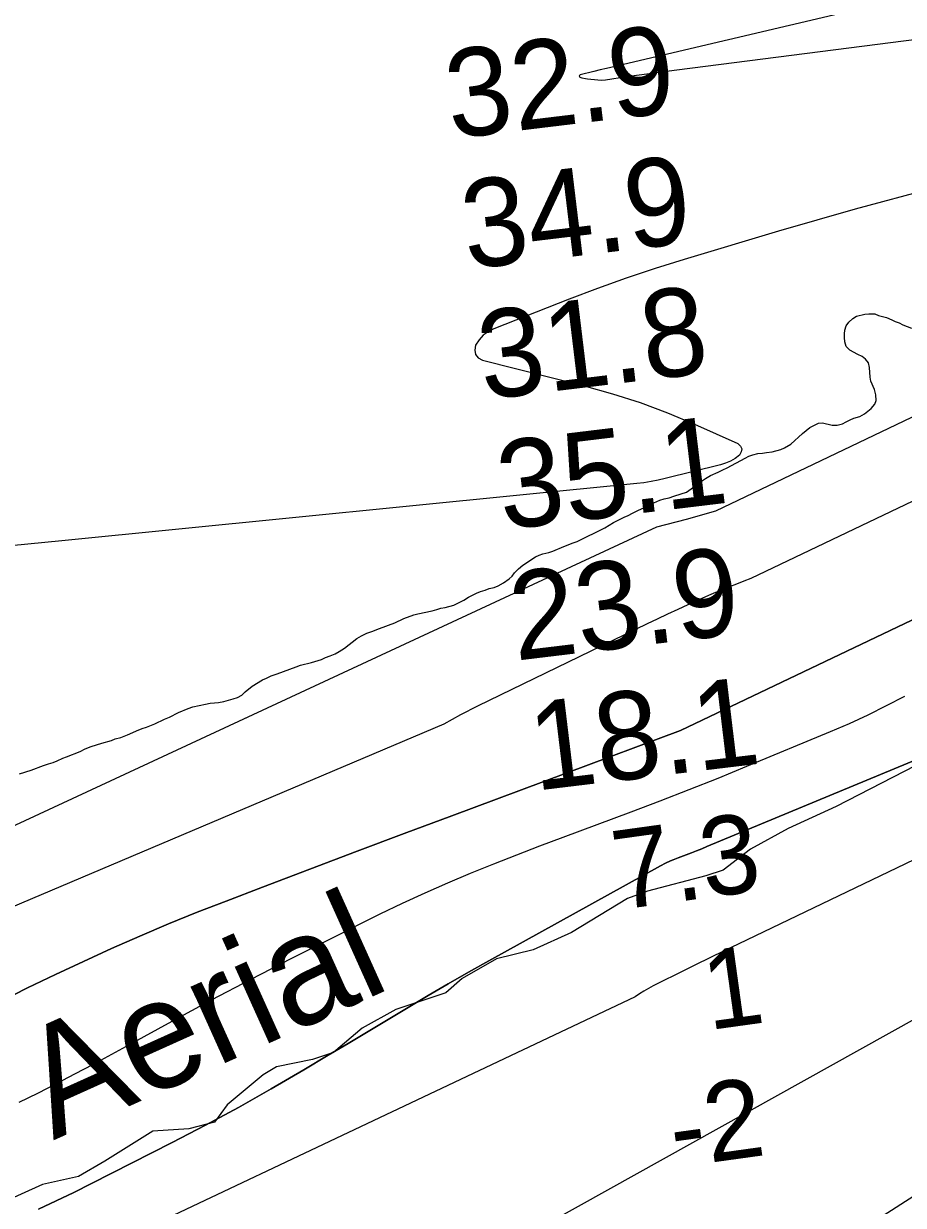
# Model space of a CAD drawing. Extents: x 3219052 to 3256913, y 800770 to 826146.
# Drawn here: x 3224915 to 3225585, y 815967 to 816866 of the extents above; entities that cross this region are included whole.
import ezdxf

# ---------------------------------------------------------------- set-up
doc = ezdxf.new("R2010")
doc.units = 0
for name, color, linetype in [('V-RIVR-EDGE', 7, 'Continuous'), ('V-RIVR-IDEN', 7, 'Continuous'), ('V-RIVR-RANG', 7, 'Continuous'), ('V-SITE-VEGE', 7, 'Continuous'), ('V-TOPO-DPTH', 7, 'Continuous'), ('V-TOPO-MAJR', 7, 'Continuous'), ('V-TOPO-MINR', 7, 'Continuous'), ('V-TOPO-WATR', 7, 'Continuous')]:
    doc.layers.add(name, color=color, linetype=linetype)

msp = doc.modelspace()

# ---------------------------------------------------------------- linework, layer by layer
at = {"layer": 'V-RIVR-EDGE'}
msp.add_lwpolyline([(3225602.27, 816305.95), (3225533.5, 816270.48), (3225496.95, 816253.61), (3225468.22, 816238.04), (3225447.32, 816222.01), (3225434.27, 816217.69), (3225389.9, 816206.06), (3225374.67, 816200.45), (3225332.01, 816174.48), (3225302.85, 816161.51), (3225275.02, 816154.62), (3225248.9, 816139.47), (3225236.27, 816128.64), (3225198.42, 816116.12), (3225172.74, 816101.84), (3225150.96, 816083.21), (3225134.86, 816078.03), (3225107.46, 816072.45), (3225097.45, 816066.39), (3225070.01, 816043.42), (3225060.41, 816030.4), (3225040.84, 816025.23), (3225013.45, 816023.56), (3224976.88, 816000.61), (3224956.86, 815988.93), (3224929.46, 815982.91), (3224899.87, 815969.51)], dxfattribs=at)
at = {"layer": 'V-SITE-VEGE'}
for p, q in [((3225546.11, 816641.72), (3225548.95, 816643.43)), ((3225548.95, 816643.43), (3225555.15, 816645)), ((3225555.15, 816645), (3225558.33, 816645.2)), ((3225558.33, 816645.2), (3225562.86, 816645.08)), ((3225562.86, 816645.08), (3225565.56, 816643.94)), ((3225565.56, 816643.94), (3225571.62, 816642.32)), ((3225540, 816632.76), (3225540.98, 816635.96)), ((3225540.98, 816635.96), (3225542.96, 816638.83)), ((3225542.96, 816638.83), (3225546.11, 816641.72)), ((3225571.62, 816642.32), (3225575.67, 816640.69)), ((3225575.67, 816640.69), (3225578.36, 816639.37)), ((3225578.36, 816639.37), (3225581.4, 816638.23)), ((3225581.4, 816638.23), (3225584.09, 816636.92)), ((3225584.09, 816636.92), (3225590.67, 816634.3)), ((3225539.7, 816630.07), (3225540, 816632.76)), ((3225539.73, 816627.22), (3225539.7, 816630.07)), ((3225539.93, 816623.86), (3225539.73, 816627.22)), ((3225540.97, 816620.35), (3225539.93, 816623.86)), ((3225543.85, 816617.53), (3225540.97, 816620.35)), ((3225549.76, 816614.23), (3225543.85, 816617.53)), ((3225553.14, 816612.76), (3225549.76, 816614.23)), ((3225555.67, 816610.77), (3225553.14, 816612.76)), ((3225557.89, 816607.78), (3225555.67, 816610.77)), ((3225558.76, 816604.26), (3225557.89, 816607.78)), ((3225559.34, 816597.05), (3225558.76, 816604.26)), ((3225559.71, 816594.03), (3225559.34, 816597.05)), ((3225562.46, 816587.52), (3225559.71, 816594.03)), ((3225563.51, 816583.67), (3225562.46, 816587.52)), ((3225563.9, 816579.31), (3225563.51, 816583.67)), ((3225554.94, 816569.15), (3225557.44, 816571.19)), ((3225557.44, 816571.19), (3225560.1, 816573.06)), ((3225560.1, 816573.06), (3225562.75, 816576.45)), ((3225562.75, 816576.45), (3225563.9, 816579.31)), ((3225516.94, 816560.52), (3225519.94, 816561.9)), ((3225519.94, 816561.9), (3225522.96, 816562.26)), ((3225522.96, 816562.26), (3225530.36, 816560.5)), ((3225538.07, 816561.42), (3225541.07, 816562.96)), ((3225541.07, 816562.96), (3225544.08, 816564.67)), ((3225544.08, 816564.67), (3225546.92, 816565.71)), ((3225546.92, 816565.71), (3225551.44, 816567.1)), ((3225551.44, 816567.1), (3225554.94, 816569.15)), ((3225498.8, 816546.07), (3225507.77, 816554.05)), ((3225507.77, 816554.05), (3225513.43, 816558.64)), ((3225513.43, 816558.64), (3225516.94, 816560.52)), ((3225530.36, 816560.5), (3225534.22, 816560.37)), ((3225534.22, 816560.37), (3225538.07, 816561.42)), ((3225494.13, 816543.33), (3225498.8, 816546.07)), ((3225450.32, 816527.93), (3225464.17, 816535.29)), ((3225464.17, 816535.29), (3225467.01, 816537.01)), ((3225467.01, 816537.01), (3225469.85, 816538.04)), ((3225469.85, 816538.04), (3225473.87, 816538.92)), ((3225473.87, 816538.92), (3225477.22, 816539.12)), ((3225477.22, 816539.12), (3225480.41, 816539.66)), ((3225480.41, 816539.66), (3225484.76, 816540.21)), ((3225484.76, 816540.21), (3225491.29, 816541.96)), ((3225491.29, 816541.96), (3225494.13, 816543.33)), ((3225443.64, 816524.84), (3225447.15, 816526.56)), ((3225447.15, 816526.56), (3225450.32, 816527.93)), ((3225423.13, 816512.04), (3225429.29, 816516.8)), ((3225429.29, 816516.8), (3225433.96, 816519.87)), ((3225433.96, 816519.87), (3225437.63, 816522.09)), ((3225437.63, 816522.09), (3225443.64, 816524.84)), ((3225409.77, 816506.53), (3225415.46, 816508.27)), ((3225415.46, 816508.27), (3225419.47, 816509.65)), ((3225419.47, 816509.65), (3225423.13, 816512.04)), ((3225389.38, 816498.76), (3225392.38, 816500.47)), ((3225392.38, 816500.47), (3225399.23, 816503.4)), ((3225399.23, 816503.4), (3225402.58, 816504.44)), ((3225402.58, 816504.44), (3225406.26, 816505.32)), ((3225406.26, 816505.32), (3225409.77, 816506.53)), ((3225363.83, 816486.41), (3225372.18, 816490.53)), ((3225372.18, 816490.53), (3225375.02, 816491.73)), ((3225375.02, 816491.73), (3225378.36, 816493.44)), ((3225378.36, 816493.44), (3225389.38, 816498.76)), ((3225336.29, 816472.02), (3225357.33, 816482.31)), ((3225357.33, 816482.31), (3225363.83, 816486.41)), ((3225333.29, 816470.98), (3225336.29, 816472.02)), ((3225310.21, 816462.68), (3225314.73, 816463.74)), ((3225314.73, 816463.74), (3225317.75, 816464.61)), ((3225317.75, 816464.61), (3225326.27, 816468.22)), ((3225326.27, 816468.22), (3225333.29, 816470.98)), ((3225291.54, 816451.24), (3225295.04, 816453.96)), ((3225295.04, 816453.96), (3225297.7, 816455.84)), ((3225297.7, 816455.84), (3225301.7, 816458.57)), ((3225301.7, 816458.57), (3225304.53, 816460.28)), ((3225304.53, 816460.28), (3225307.37, 816461.65)), ((3225307.37, 816461.65), (3225310.21, 816462.68)), ((3225284.57, 816443.62), (3225286.9, 816445.66)), ((3225286.9, 816445.66), (3225288.72, 816448.19)), ((3225288.72, 816448.19), (3225291.54, 816451.24)), ((3225266.2, 816435.03), (3225269.38, 816436.24)), ((3225269.38, 816436.24), (3225273.23, 816437.12)), ((3225273.23, 816437.12), (3225276.24, 816438.33)), ((3225276.24, 816438.33), (3225280.24, 816440.55)), ((3225280.24, 816440.55), (3225284.57, 816443.62)), ((3225242.5, 816423.54), (3225250.01, 816427.31)), ((3225250.01, 816427.31), (3225253.67, 816429.7)), ((3225253.67, 816429.7), (3225259.68, 816432.78)), ((3225259.68, 816432.78), (3225262.86, 816433.99)), ((3225262.86, 816433.99), (3225266.2, 816435.03)), ((3225215.04, 816417.04), (3225225.93, 816419.34)), ((3225225.93, 816419.34), (3225229.44, 816420.21)), ((3225229.44, 816420.21), (3225232.45, 816421.25)), ((3225232.45, 816421.25), (3225235.8, 816421.79)), ((3225235.8, 816421.79), (3225242.5, 816423.54)), ((3225192.65, 816408.24), (3225197.5, 816410.14)), ((3225197.5, 816410.14), (3225204.34, 816413.4)), ((3225204.34, 816413.4), (3225212.03, 816416.17)), ((3225212.03, 816416.17), (3225215.04, 816417.04)), ((3225168.59, 816398.26), (3225172.26, 816400.31)), ((3225172.26, 816400.31), (3225176.26, 816402.37)), ((3225176.26, 816402.37), (3225180.78, 816403.76)), ((3225180.78, 816403.76), (3225183.79, 816405.13)), ((3225183.79, 816405.13), (3225192.65, 816408.24)), ((3225159.27, 816390.77), (3225168.59, 816398.26)), ((3225134.21, 816379.94), (3225141.74, 816382.37)), ((3225141.74, 816382.37), (3225144.75, 816383.74)), ((3225144.75, 816383.74), (3225148.42, 816385.12)), ((3225148.42, 816385.12), (3225152.1, 816386.67)), ((3225152.1, 816386.67), (3225155.27, 816388.38)), ((3225155.27, 816388.38), (3225159.27, 816390.77)), ((3225108.12, 816371.44), (3225122.5, 816376.79)), ((3225122.5, 816376.79), (3225125.67, 816377.83)), ((3225125.67, 816377.83), (3225134.21, 816379.94)), ((3225089.09, 816362.01), (3225096.76, 816366.79)), ((3225096.76, 816366.79), (3225099.94, 816368.16)), ((3225099.94, 816368.16), (3225103.44, 816369.88)), ((3225103.44, 816369.88), (3225108.12, 816371.44)), ((3225077.94, 816353.33), (3225081.11, 816355.04)), ((3225081.11, 816355.04), (3225083.6, 816357.59)), ((3225083.6, 816357.59), (3225089.09, 816362.01)), ((3225040.27, 816345.05), (3225043.78, 816346.26)), ((3225043.78, 816346.26), (3225053.49, 816348.37)), ((3225053.49, 816348.37), (3225057.01, 816348.92)), ((3225057.01, 816348.92), (3225060.36, 816349.29)), ((3225060.36, 816349.29), (3225063.38, 816349.48)), ((3225063.38, 816349.48), (3225067.4, 816350.37)), ((3225067.4, 816350.37), (3225074.6, 816352.29)), ((3225074.6, 816352.29), (3225077.94, 816353.33)), ((3225022.4, 816336.97), (3225026.07, 816338.35)), ((3225026.07, 816338.35), (3225032.92, 816341.95)), ((3225032.92, 816341.95), (3225040.27, 816345.05)), ((3225001.01, 816328.02), (3225005.36, 816329.75)), ((3225005.36, 816329.75), (3225008.7, 816330.78)), ((3225008.7, 816330.78), (3225014.88, 816333.37)), ((3225014.88, 816333.37), (3225022.4, 816336.97)), ((3224974.6, 816318.68), (3224981.96, 816320.6)), ((3224981.96, 816320.6), (3224984.8, 816321.81)), ((3224984.8, 816321.81), (3224989.15, 816323.03)), ((3224989.15, 816323.03), (3224994.16, 816324.93)), ((3224994.16, 816324.93), (3224998.17, 816326.64)), ((3224998.17, 816326.64), (3225001.01, 816328.02)), ((3224947.86, 816308.16), (3224958.05, 816312.3)), ((3224958.05, 816312.3), (3224961.89, 816314.18)), ((3224961.89, 816314.18), (3224966.4, 816316.07)), ((3224966.4, 816316.07), (3224974.6, 816318.68)), ((3224920.95, 816297.97), (3224930.14, 816301.6)), ((3224930.14, 816301.6), (3224934.15, 816302.81)), ((3224934.15, 816302.81), (3224937.5, 816304.02)), ((3224937.5, 816304.02), (3224940.67, 816305.23)), ((3224940.67, 816305.23), (3224944.85, 816307.12)), ((3224944.85, 816307.12), (3224947.86, 816308.16)), ((3224912.08, 816295.36), (3224920.95, 816297.97))]:
    msp.add_line(p, q, dxfattribs=at)
at = {"layer": 'V-TOPO-DPTH'}
for points in [[(3224896.89, 816121.97), (3224918.03, 816132.4), (3224939.26, 816142.65), (3224960.62, 816152.62), (3224982.07, 816162.41), (3225003.66, 816171.87), (3225025.35, 816181.09), (3225047.2, 816189.94), (3225069.15, 816198.54), (3225096.92, 816209.15), (3225132.85, 816222.83), (3225168.8, 816236.44), (3225204.79, 816249.96), (3225240.81, 816263.42), (3225414.89, 816328.2), (3225844.03, 816532.73)], [(3224926.34, 815964.19), (3224939.94, 815970.43), (3224953.42, 815976.92), (3224966.83, 815983.58), (3225028.12, 816014.77), (3225053.47, 816027.99), (3225078.64, 816041.55), (3225103.52, 816055.62), (3225128.22, 816070.02), (3225146.9, 816081.18), (3225162.12, 816090.27), (3225177.32, 816099.37), (3225192.51, 816108.5), (3225207.7, 816117.63), (3225222.93, 816126.69), (3225238.23, 816135.64), (3225253.62, 816144.41), (3225269.08, 816153.07), (3225399.73, 816225.3), (3225403.49, 816227.26), (3225407.34, 816229.03), (3225409.3, 816229.86), (3225413.24, 816231.44), (3225415.22, 816232.2), (3225419.21, 816233.69), (3225423.19, 816235.2), (3225427.16, 816236.74), (3225431.11, 816238.32), (3225435.05, 816239.92), (3225639.8, 816324.85)], [(3225639.8, 816324.85), (3225435.05, 816239.92), (3225431.11, 816238.32), (3225427.16, 816236.74), (3225423.19, 816235.2), (3225419.21, 816233.69), (3225415.22, 816232.2), (3225413.24, 816231.44), (3225409.3, 816229.86), (3225407.34, 816229.03), (3225403.49, 816227.26), (3225399.73, 816225.3), (3225269.08, 816153.07), (3225253.62, 816144.41), (3225238.23, 816135.64), (3225222.93, 816126.69), (3225207.7, 816117.63), (3225192.51, 816108.5), (3225177.32, 816099.37), (3225162.12, 816090.27), (3225146.9, 816081.18), (3225128.22, 816070.02), (3225103.52, 816055.62), (3225078.64, 816041.55), (3225053.47, 816027.99), (3225028.12, 816014.77), (3224966.83, 815983.58), (3224953.42, 815976.92), (3224939.94, 815970.43), (3224926.34, 815964.19)], [(3225615.93, 816121.26), (3224931.3, 815740.25)], [(3225615.93, 816121.26), (3224931.3, 815740.25)]]:
    msp.add_lwpolyline(points, dxfattribs=at)
at = {"layer": 'V-TOPO-MAJR'}
for points in [[(3225826.99, 816942.19), (3225358.73, 816831.88), (3225353.88, 816830.73), (3225349.04, 816829.55), (3225338.53, 816826.97), (3225338.06, 816826.56), (3225337.84, 816826.14), (3225338, 816825.69), (3225338.42, 816825.23), (3225339.8, 816824.76), (3225342.63, 816824.1), (3225344.07, 816823.9), (3225351.92, 816823.15), (3225354.85, 816823.04), (3225357.77, 816823.29), (3225373.93, 816825.62), (3225383.48, 816826.98), (3225393.02, 816828.31), (3225402.58, 816829.58), (3225412.14, 816830.83), (3226064.38, 816914.38)], [(3225606.35, 816740.51), (3225547.84, 816724.67), (3225489.55, 816707.97), (3225417.73, 816686.56), (3225395.61, 816679.66), (3225373.62, 816672.39), (3225351.82, 816664.57), (3225330.15, 816656.38), (3225272.77, 816633.87), (3225268.5, 816631.61), (3225264.7, 816628.84), (3225261.61, 816625.3), (3225258.99, 816621.25), (3225258.39, 816617.52), (3225258.88, 816614.29), (3225261.02, 816611.81), (3225264.24, 816609.84), (3225341.75, 816590.32), (3225363.12, 816584.34), (3225384.25, 816577.63), (3225405, 816569.83), (3225425.49, 816561.3), (3225458.48, 816546.54), (3225460.51, 816544.57), (3225461.56, 816542.47), (3225461.16, 816540.15), (3225459.78, 816537.69), (3225456.48, 816535.23), (3225453.01, 816533.11), (3225449.27, 816531.5), (3225445.36, 816530.23), (3225403.22, 816519.8), (3225397.88, 816518.6), (3225392.51, 816517.55), (3225387.1, 816516.74), (3225381.66, 816516.08), (3224944.3, 816472.48), (3224905.33, 816468.65)]]:
    msp.add_lwpolyline(points, dxfattribs=at)
at = {"layer": 'V-TOPO-MINR'}
for points in [[(3226896.77, 817144.39), (3226152.02, 816821.42), (3226120.61, 816812.75), (3226089.11, 816804.46), (3225441.46, 816495.05), (3225419.12, 816488.77), (3225396.7, 816482.84), (3224771.09, 816192.45), (3224740.17, 816182.94), (3224332.43, 816001.55), (3224293.96, 815985.45), (3224176.45, 815938.48), (3224136.02, 815922.49), (3224095.52, 815906.69), (3224060.2, 815893.19)], [(3226100.31, 816745.28), (3225468.39, 816443.81), (3225463.01, 816441.74), (3225457.64, 816439.64), (3225452.29, 816437.51), (3225446.95, 816435.36), (3225441.62, 816433.15), (3225436.32, 816430.9), (3225431.04, 816428.59), (3225425.78, 816426.24), (3225420.62, 816423.89), (3225412.8, 816420.3), (3225405.01, 816416.67), (3225397.24, 816412.99), (3225389.49, 816409.27), (3225260.58, 816346.74), (3225247.6, 816340.12), (3225234.8, 816333.16), (3224828.39, 816160.84)], [(3226852.52, 816672.62), (3226258.26, 816393.72), (3226251.99, 816391.62), (3226245.74, 816389.49), (3226239.5, 816387.31), (3226233.28, 816385.09), (3226227.44, 816382.35), (3226222.05, 816379), (3226217.35, 816374.74), (3225469.38, 815895.07), (3224836.76, 815589.56)], [(3225844.03, 816532.73), (3225414.89, 816328.2), (3225240.81, 816263.42), (3225204.79, 816249.96), (3225168.8, 816236.44), (3225132.85, 816222.83), (3225096.92, 816209.15), (3225069.15, 816198.54), (3225047.2, 816189.94), (3225025.35, 816181.09), (3225003.66, 816171.87), (3224982.07, 816162.41), (3224960.62, 816152.62), (3224939.26, 816142.65), (3224918.03, 816132.4), (3224896.89, 816121.97)], [(3225585.28, 816354.19), (3225571.41, 816346.88), (3225557.39, 816339.88), (3225543.16, 816333.34), (3225528.77, 816327.11), (3225465.16, 816300.75), (3225443.29, 816291.82), (3225421.35, 816283.06), (3225399.32, 816274.53), (3225377.23, 816266.16), (3225325.38, 816246.84), (3225307.71, 816240.17), (3225290.09, 816233.4), (3225272.53, 816226.47), (3225255.01, 816219.44), (3225237.6, 816212.14), (3225220.31, 816204.58), (3225203.2, 816196.63), (3225186.2, 816188.43), (3225148.76, 816169.86), (3225118.31, 816154.52), (3225087.99, 816138.94), (3225057.85, 816122.99), (3225027.84, 816106.81), (3224995.84, 816089.31), (3224981.9, 816081.74), (3224967.94, 816074.22), (3224953.93, 816066.78), (3224939.9, 816059.39), (3224925.77, 816052.19), (3224911.54, 816045.21)], [(3225599.87, 816233.46), (3225579.24, 816223.45), (3225459.29, 816165.94), (3225448.26, 816160.63), (3225437.25, 816155.29), (3225426.25, 816149.92), (3225415.26, 816144.51), (3225397.68, 816135.82), (3225394.11, 816133.98), (3225390.59, 816132.04), (3225387.13, 816129.99), (3225383.73, 816127.84), (3225380.38, 816125.61), (3224805.82, 815853.86)], [(3225615.93, 816121.26), (3224931.3, 815740.25)]]:
    msp.add_lwpolyline(points, dxfattribs=at)
at = {"layer": 'V-TOPO-WATR'}
msp.add_lwpolyline([(3225639.8, 816324.85), (3225435.05, 816239.92), (3225431.11, 816238.32), (3225427.16, 816236.74), (3225423.19, 816235.2), (3225419.21, 816233.69), (3225415.22, 816232.2), (3225413.24, 816231.44), (3225409.3, 816229.86), (3225407.34, 816229.03), (3225403.49, 816227.26), (3225399.73, 816225.3), (3225269.08, 816153.07), (3225253.62, 816144.41), (3225238.23, 816135.64), (3225222.93, 816126.69), (3225207.7, 816117.63), (3225192.51, 816108.5), (3225177.32, 816099.37), (3225162.12, 816090.27), (3225146.9, 816081.18), (3225128.22, 816070.02), (3225103.52, 816055.62), (3225078.64, 816041.55), (3225053.47, 816027.99), (3225028.12, 816014.77), (3224966.83, 815983.58), (3224953.42, 815976.92), (3224939.94, 815970.43), (3224926.34, 815964.19)], dxfattribs=at)

# ---------------------------------------------------------------- texts
at = {"layer": 'V-RIVR-IDEN'}
msp.add_text('Aerial', height=83, rotation=24.25348, dxfattribs=at).set_placement((3224937.69, 816016.37))
at = {"layer": 'V-RIVR-RANG'}
for s, height, rotation, p in [('32.9', 67, 6.88833, (3225240.4, 816778.27)), ('34.9', 67, 6.88833, (3225252.65, 816679.02)), ('31.8', 67, 6.88833, (3225265.16, 816579.8)), ('35.1', 67, 6.88833, (3225279.76, 816480.84)), ('23.9', 67, 6.88833, (3225289.39, 816381.28)), ('18.1', 67, 6.88833, (3225304.25, 816282.35)), ('7.3', 60, 7.88961, (3225367.74, 816191.68)), ('1', 60, 7.88961, (3225436.38, 816100.24)), ('-2', 60, 7.88961, (3225410.48, 815995.71))]:
    msp.add_text(s, height=height, rotation=rotation, dxfattribs=at).set_placement(p)

doc.saveas('drawing.dxf')
